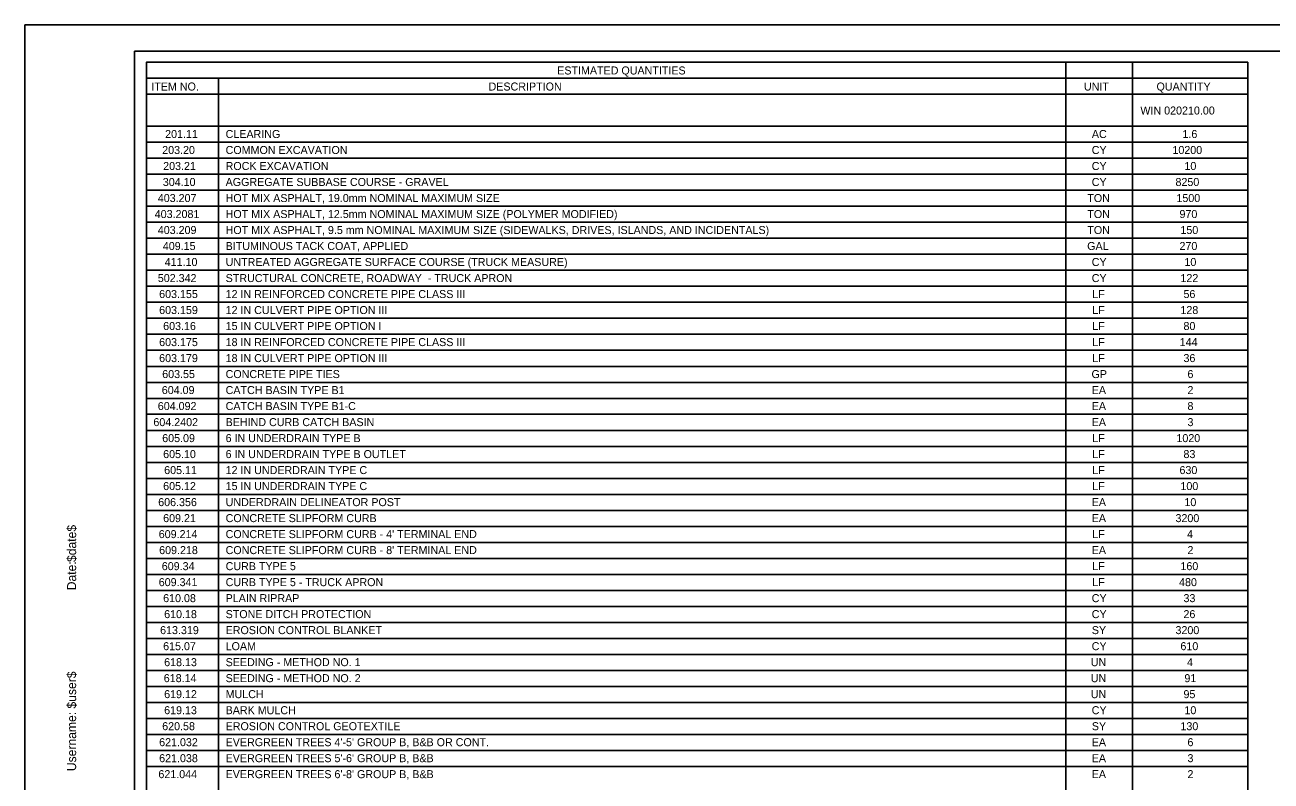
# Model space of a CAD drawing. Extents: x 2075518.1 to 2075585.6, y 1172412.5 to 1172434.5.
# Drawn here: x 2075518.14 to 2075536.53, y 1172423.33 to 1172434.49 of the extents above; entities that cross this region are included whole.
import ezdxf

# ---------------------------------------------------------------- set-up
doc = ezdxf.new("R2010")
doc.units = 0
doc.layers.add('Border', color=7, linetype='Continuous')
doc.layers.add('PLOT BOUNDARY', color=7, linetype='Continuous')

msp = doc.modelspace()

# ---------------------------------------------------------------- linework, layer by layer
at = {"layer": 'Border'}
for p, q in [((2075551.755, 1172434.098), (2075519.755, 1172434.098)), ((2075519.755, 1172434.098), (2075519.755, 1172413.098)), ((2075533.496, 1172433.936), (2075533.496, 1172414.092)), ((2075534.481, 1172433.936), (2075534.481, 1172414.092)), ((2075519.93, 1172433.7), (2075536.182, 1172433.7)), ((2075520.993, 1172433.7), (2075520.993, 1172432.991)), ((2075530.246, 1172433.7), (2075531.231, 1172433.7)), ((2075531.231, 1172433.7), (2075536.182, 1172433.7)), ((2075519.93, 1172433.463), (2075536.182, 1172433.463)), ((2075519.93, 1172432.991), (2075536.182, 1172432.991)), ((2075520.993, 1172432.994), (2075520.993, 1172414.092)), ((2075519.93, 1172432.755), (2075536.182, 1172432.755)), ((2075519.93, 1172432.518), (2075536.182, 1172432.518)), ((2075519.93, 1172432.282), (2075536.182, 1172432.282)), ((2075519.93, 1172432.046), (2075536.182, 1172432.046)), ((2075519.93, 1172431.81), (2075536.182, 1172431.81)), ((2075519.93, 1172431.573), (2075536.182, 1172431.573)), ((2075519.93, 1172431.337), (2075536.182, 1172431.337)), ((2075519.93, 1172431.101), (2075536.182, 1172431.101)), ((2075519.93, 1172430.865), (2075536.182, 1172430.865)), ((2075519.93, 1172430.629), (2075536.182, 1172430.629)), ((2075519.93, 1172430.392), (2075536.182, 1172430.392)), ((2075519.93, 1172430.156), (2075536.182, 1172430.156)), ((2075519.93, 1172429.92), (2075536.182, 1172429.92)), ((2075519.93, 1172429.684), (2075536.182, 1172429.684)), ((2075519.93, 1172429.447), (2075536.182, 1172429.447)), ((2075519.93, 1172429.211), (2075536.182, 1172429.211)), ((2075519.93, 1172428.975), (2075536.182, 1172428.975)), ((2075519.93, 1172428.739), (2075536.182, 1172428.739)), ((2075519.93, 1172428.502), (2075536.182, 1172428.502)), ((2075519.93, 1172428.266), (2075536.182, 1172428.266)), ((2075519.93, 1172428.03), (2075536.182, 1172428.03)), ((2075519.93, 1172427.794), (2075536.182, 1172427.794)), ((2075519.93, 1172427.557), (2075536.182, 1172427.557)), ((2075519.93, 1172427.321), (2075536.182, 1172427.321)), ((2075519.93, 1172427.085), (2075536.182, 1172427.085)), ((2075519.93, 1172426.849), (2075536.182, 1172426.849)), ((2075519.93, 1172426.613), (2075536.182, 1172426.613)), ((2075519.93, 1172426.376), (2075536.182, 1172426.376)), ((2075519.93, 1172426.14), (2075536.182, 1172426.14)), ((2075519.93, 1172425.904), (2075536.182, 1172425.904)), ((2075519.93, 1172425.668), (2075536.182, 1172425.668)), ((2075519.93, 1172425.431), (2075536.182, 1172425.431)), ((2075519.93, 1172425.195), (2075536.182, 1172425.195)), ((2075519.93, 1172424.959), (2075536.182, 1172424.959)), ((2075519.93, 1172424.959), (2075536.182, 1172424.959)), ((2075519.93, 1172424.723), (2075536.182, 1172424.723)), ((2075519.93, 1172424.486), (2075536.182, 1172424.486)), ((2075519.93, 1172424.25), (2075536.182, 1172424.25)), ((2075519.93, 1172424.014), (2075536.182, 1172424.014)), ((2075519.93, 1172423.778), (2075536.182, 1172423.778)), ((2075519.93, 1172423.542), (2075536.182, 1172423.542))]:
    msp.add_line(p, q, dxfattribs=at)
msp.add_lwpolyline([(2075536.182, 1172414.092), (2075519.93, 1172414.092), (2075519.93, 1172433.936), (2075536.182, 1172433.936), (2075536.182, 1172414.092)], dxfattribs=at)
at = {"layer": 'PLOT BOUNDARY'}
msp.add_lwpolyline([(2075518.136, 1172412.486), (2075552.136, 1172412.486), (2075552.136, 1172434.486), (2075518.136, 1172434.486)], close=True, dxfattribs=at)

# ---------------------------------------------------------------- texts
at = {"layer": 'Border'}
for s, height, p in [('ESTIMATED QUANTITIES', 0.11811, (2075525.991, 1172433.755)), ('ITEM NO.', 0.1181, (2075520.001, 1172433.518)), ('DESCRIPTION', 0.11811, (2075524.978, 1172433.518)), ('UNIT', 0.1181, (2075533.764, 1172433.518)), ('QUANTITY', 0.1181, (2075534.835, 1172433.518)), ('WIN 020210.00', 0.11811, (2075534.597, 1172433.164)), ('201.11', 0.1181, (2075520.205, 1172432.817)), ('CLEARING', 0.1181, (2075521.098, 1172432.817)), ('AC', 0.1181, (2075533.881, 1172432.817)), ('1.6', 0.1181, (2075535.218, 1172432.817)), ('203.20', 0.1181, (2075520.162, 1172432.581)), ('COMMON EXCAVATION', 0.11811, (2075521.098, 1172432.581)), ('CY', 0.1181, (2075533.879, 1172432.581)), ('10200', 0.1181, (2075535.07, 1172432.581)), ('203.21', 0.1181, (2075520.176, 1172432.345)), ('ROCK EXCAVATION', 0.11811, (2075521.098, 1172432.345)), ('CY', 0.1181, (2075533.879, 1172432.345)), ('10', 0.1181, (2075535.247, 1172432.345)), ('304.10', 0.1181, (2075520.171, 1172432.109)), ('AGGREGATE SUBBASE COURSE - GRAVEL', 0.11811, (2075521.098, 1172432.109)), ('CY', 0.1181, (2075533.879, 1172432.109)), ('8250', 0.1181, (2075535.115, 1172432.109)), ('403.207', 0.1181, (2075520.097, 1172431.872)), ('HOT MIX ASPHALT, 19.0mm NOMINAL MAXIMUM SIZE', 0.11811, (2075521.098, 1172431.872)), ('TON', 0.1181, (2075533.814, 1172431.872)), ('1500', 0.1181, (2075535.129, 1172431.872)), ('403.2081', 0.1181, (2075520.052, 1172431.636)), ('HOT MIX ASPHALT, 12.5mm NOMINAL MAXIMUM SIZE (POLYMER MODIFIED)', 0.11811, (2075521.098, 1172431.636)), ('TON', 0.1181, (2075533.814, 1172431.636)), ('970', 0.1181, (2075535.174, 1172431.636)), ('403.209', 0.1181, (2075520.097, 1172431.4)), ('HOT MIX ASPHALT, 9.5 mm NOMINAL MAXIMUM SIZE (SIDEWALKS, DRIVES, ISLANDS, AND INCIDENTALS)', 0.11811, (2075521.098, 1172431.4)), ('TON', 0.1181, (2075533.814, 1172431.4)), ('150', 0.1181, (2075535.188, 1172431.4)), ('409.15', 0.1181, (2075520.171, 1172431.164)), ('BITUMINOUS TACK COAT, APPLIED', 0.11811, (2075521.098, 1172431.164)), ('GAL', 0.1181, (2075533.812, 1172431.164)), ('270', 0.1181, (2075535.174, 1172431.164)), ('411.10', 0.1181, (2075520.199, 1172430.928)), ('UNTREATED AGGREGATE SURFACE COURSE (TRUCK MEASURE)', 0.11811, (2075521.098, 1172430.928)), ('CY', 0.1181, (2075533.879, 1172430.928)), ('10', 0.1181, (2075535.247, 1172430.928)), ('502.342', 0.1181, (2075520.097, 1172430.691)), ('STRUCTURAL CONCRETE, ROADWAY  - TRUCK APRON', 0.11811, (2075521.098, 1172430.691)), ('CY', 0.1181, (2075533.879, 1172430.691)), ('122', 0.1181, (2075535.188, 1172430.691)), ('603.155', 0.1181, (2075520.117, 1172430.455)), ('12 IN REINFORCED CONCRETE PIPE CLASS III', 0.11811, (2075521.098, 1172430.455)), ('LF', 0.1181, (2075533.887, 1172430.455)), ('56', 0.1181, (2075535.233, 1172430.455)), ('603.159', 0.1181, (2075520.117, 1172430.219)), ('12 IN CULVERT PIPE OPTION III', 0.11811, (2075521.098, 1172430.219)), ('LF', 0.1181, (2075533.887, 1172430.219)), ('128', 0.1181, (2075535.188, 1172430.219)), ('603.16', 0.1181, (2075520.176, 1172429.983)), ('15 IN CULVERT PIPE OPTION I', 0.11811, (2075521.098, 1172429.983)), ('LF', 0.1181, (2075533.887, 1172429.983)), ('80', 0.1181, (2075535.233, 1172429.983)), ('603.175', 0.1181, (2075520.117, 1172429.746)), ('18 IN REINFORCED CONCRETE PIPE CLASS III', 0.11811, (2075521.098, 1172429.746)), ('LF', 0.1181, (2075533.887, 1172429.746)), ('144', 0.1181, (2075535.177, 1172429.746)), ('603.179', 0.1181, (2075520.117, 1172429.51)), ('18 IN CULVERT PIPE OPTION III', 0.11811, (2075521.098, 1172429.51)), ('LF', 0.1181, (2075533.887, 1172429.51)), ('36', 0.1181, (2075535.233, 1172429.51)), ('603.55', 0.1181, (2075520.162, 1172429.274)), ('CONCRETE PIPE TIES', 0.11811, (2075521.098, 1172429.274)), ('GP', 0.1181, (2075533.876, 1172429.274)), ('6', 0.118, (2075535.292, 1172429.274)), ('604.09', 0.1181, (2075520.156, 1172429.038)), ('CATCH BASIN TYPE B1', 0.11811, (2075521.098, 1172429.038)), ('EA', 0.1181, (2075533.879, 1172429.038)), ('2', 0.118, (2075535.292, 1172429.038)), ('604.092', 0.1181, (2075520.097, 1172428.802)), ('CATCH BASIN TYPE B1-C', 0.11811, (2075521.098, 1172428.802)), ('EA', 0.1181, (2075533.879, 1172428.802)), ('8', 0.118, (2075535.292, 1172428.802)), ('604.2402', 0.1181, (2075520.032, 1172428.565)), ('BEHIND CURB CATCH BASIN', 0.11811, (2075521.098, 1172428.565)), ('EA', 0.1181, (2075533.879, 1172428.565)), ('3', 0.118, (2075535.292, 1172428.565)), ('605.09', 0.1181, (2075520.162, 1172428.329)), ('6 IN UNDERDRAIN TYPE B', 0.11811, (2075521.098, 1172428.329)), ('LF', 0.1181, (2075533.887, 1172428.329)), ('1020', 0.1181, (2075535.129, 1172428.329)), ('605.10', 0.1181, (2075520.176, 1172428.093)), ('6 IN UNDERDRAIN TYPE B OUTLET', 0.11811, (2075521.098, 1172428.093)), ('LF', 0.1181, (2075533.887, 1172428.093)), ('83', 0.1181, (2075535.233, 1172428.093)), ('605.11', 0.1181, (2075520.191, 1172427.857)), ('12 IN UNDERDRAIN TYPE C', 0.11811, (2075521.098, 1172427.857)), ('LF', 0.1181, (2075533.887, 1172427.857)), ('630', 0.1181, (2075535.174, 1172427.857)), ('605.12', 0.1181, (2075520.176, 1172427.621)), ('15 IN UNDERDRAIN TYPE C', 0.11811, (2075521.098, 1172427.621)), ('LF', 0.1181, (2075533.887, 1172427.621)), ('100', 0.1181, (2075535.188, 1172427.621)), ('606.356', 0.1181, (2075520.103, 1172427.384)), ('UNDERDRAIN DELINEATOR POST', 0.11811, (2075521.098, 1172427.384)), ('EA', 0.1181, (2075533.879, 1172427.384)), ('10', 0.1181, (2075535.247, 1172427.384)), ('609.21', 0.1181, (2075520.176, 1172427.148)), ('CONCRETE SLIPFORM CURB', 0.11811, (2075521.098, 1172427.148)), ('EA', 0.1181, (2075533.879, 1172427.148)), ('3200', 0.1181, (2075535.115, 1172427.148)), ('609.214', 0.1181, (2075520.111, 1172426.912)), ("CONCRETE SLIPFORM CURB - 4' TERMINAL END", 0.11811, (2075521.098, 1172426.912)), ('LF                ', 0.11811, (2075533.887, 1172426.912)), ('4', 0.118, (2075535.286, 1172426.912)), ('609.218', 0.1181, (2075520.117, 1172426.676)), ("CONCRETE SLIPFORM CURB - 8' TERMINAL END", 0.11811, (2075521.098, 1172426.676)), ('EA', 0.1181, (2075533.879, 1172426.676)), ('2', 0.118, (2075535.292, 1172426.676)), ('609.34', 0.1181, (2075520.156, 1172426.439)), ('CURB TYPE 5', 0.11811, (2075521.098, 1172426.439)), ('LF', 0.1181, (2075533.887, 1172426.439)), ('160', 0.1181, (2075535.188, 1172426.439)), ('609.341', 0.1181, (2075520.111, 1172426.203)), ('CURB TYPE 5 - TRUCK APRON', 0.11811, (2075521.098, 1172426.203)), ('LF                ', 0.11811, (2075533.887, 1172426.203)), ('480', 0.1181, (2075535.168, 1172426.203)), ('610.08', 0.1181, (2075520.176, 1172425.967)), ('PLAIN RIPRAP                                  ', 0.11811, (2075521.098, 1172425.967)), ('CY                ', 0.11811, (2075533.879, 1172425.967)), ('33', 0.1181, (2075535.233, 1172425.967)), ('610.18', 0.1181, (2075520.191, 1172425.731)), ('STONE DITCH PROTECTION', 0.11811, (2075521.098, 1172425.731)), ('CY                ', 0.11811, (2075533.879, 1172425.731)), ('26', 0.1181, (2075535.233, 1172425.731)), ('613.319', 0.1181, (2075520.131, 1172425.495)), ('EROSION CONTROL BLANKET', 0.11811, (2075521.098, 1172425.495)), ('SY', 0.1181, (2075533.881, 1172425.495)), ('3200', 0.1181, (2075535.115, 1172425.495)), ('615.07', 0.1181, (2075520.176, 1172425.258)), ('LOAM', 0.1181, (2075521.098, 1172425.258)), ('CY', 0.1181, (2075533.879, 1172425.258)), ('610', 0.1181, (2075535.188, 1172425.258)), ('618.13', 0.1181, (2075520.191, 1172425.022)), ('SEEDING - METHOD NO. 1  ', 0.11811, (2075521.098, 1172425.022)), ('UN                ', 0.11811, (2075533.865, 1172425.022)), ('4', 0.118, (2075535.286, 1172425.022)), ('618.14', 0.1181, (2075520.185, 1172424.786)), ('SEEDING - METHOD NO. 2  ', 0.11811, (2075521.098, 1172424.786)), ('UN                ', 0.11811, (2075533.865, 1172424.786)), ('91', 0.1181, (2075535.247, 1172424.786)), ('619.12', 0.1181, (2075520.191, 1172424.55)), ('MULCH               ', 0.11811, (2075521.098, 1172424.55)), ('UN                ', 0.11811, (2075533.865, 1172424.55)), ('95', 0.1181, (2075535.233, 1172424.55)), ('619.13', 0.1181, (2075520.191, 1172424.313)), ('BARK MULCH', 0.1181, (2075521.098, 1172424.313)), ('CY', 0.1181, (2075533.879, 1172424.313)), ('10', 0.1181, (2075535.247, 1172424.313)), ('620.58', 0.1181, (2075520.162, 1172424.077)), ('EROSION CONTROL GEOTEXTILE ', 0.11811, (2075521.098, 1172424.077)), ('SY', 0.1181, (2075533.881, 1172424.077)), ('130', 0.1181, (2075535.188, 1172424.077)), ('621.032', 0.1181, (2075520.117, 1172423.841)), ("EVERGREEN TREES 4'-5' GROUP B, B&B OR CONT.", 0.11811, (2075521.098, 1172423.841)), ('EA', 0.1181, (2075533.879, 1172423.841)), ('6', 0.118, (2075535.292, 1172423.841)), ('621.038', 0.1181, (2075520.117, 1172423.605)), ("EVERGREEN TREES 5'-6' GROUP B, B&B", 0.11811, (2075521.098, 1172423.605)), ('EA', 0.1181, (2075533.879, 1172423.605)), ('3', 0.118, (2075535.292, 1172423.605)), ('621.044', 0.1181, (2075520.106, 1172423.369)), ("EVERGREEN TREES 6'-8' GROUP B, B&B", 0.11811, (2075521.098, 1172423.369)), ('EA', 0.1181, (2075533.879, 1172423.369)), ('2', 0.118, (2075535.292, 1172423.369))]:
    msp.add_text(s, height=height, dxfattribs=at).set_placement(p)
for s, p in [('$date$', (2075518.892, 1172426.559)), ('Date:', (2075518.892, 1172426.142)), ('$user$', (2075518.892, 1172424.396)), ('Username:', (2075518.892, 1172423.472))]:
    msp.add_text(s, height=0.1339, rotation=90, dxfattribs=at).set_placement(p)

doc.saveas('drawing.dxf')
